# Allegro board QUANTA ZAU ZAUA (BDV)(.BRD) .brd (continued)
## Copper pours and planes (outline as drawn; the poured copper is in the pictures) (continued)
N18867812 on TOP (solid shape): outline of 127 points within 18.86,27.93 21.68,32.12
N21450006 on TOP (solid shape): 54.82,31.86 56.6,31.86 56.75,31.71 56.75,31.15 56.72,31.08 56.65,31.05 56.63,31.05 56.37,30.95 56.22,30.62 56.15,30.59 55.69,30.59 55.49,30.39 55.49,30.12 55.25,29.88 54.84,29.88 54.67,30.06 54.67,31.05 54.41,31.32 54.41,31.52 54.32,31.61 53.78,31.61 53.68,31.71 53.68,32.12 53.78,32.22 54.47,32.22
N22415444 on TOP (solid shape): 112.49,40.29 112.49,33.95 112.87,33.56 113.7,33.56 114.46,34.33 115.15,34.33 115.94,35.11 116.62,35.11 116.98,35.47 117.61,35.47 117.71,35.37 117.71,34.58 116.02,32.88 112.15,32.88 112.14,32.89 111.76,32.89 111.47,33.18 111.34,33.18 111.32,33.2 111.31,33.21 111.27,33.26 111.2,33.28 110.82,33.28 110.75,33.26 110.69,33.19 110.66,33.18 110.63,33.18 109.87,32.42 108.32,32.42 108.27,32.47 108.01,32.47 107.28,33.21 106.89,33.21 106.79,33.32 105.8,34.3 105.8,35.77 105.93,35.9 109.81,35.9 110.16,36.26 110.16,40.29 110.3,40.42 112.36,40.42
N22415444 on BOTTOM (solid shape): 111.55,40.19 111.55,36.63 111.55,36.61 111.54,36.6 110.26,35.32 106.15,35.32 105.54,35.93 105.54,36.9 105.61,37.02 105.63,37.15 105.61,37.28 105.55,37.39 105.54,37.4 105.54,37.55 105.55,37.56 105.61,37.67 105.62,37.79 105.6,37.91 105.54,38.03 105.54,38.26 105.54,38.29 105.66,38.43 105.69,38.59 105.66,38.75 105.54,38.9 105.54,38.92 105.54,40.33 105.73,40.51 106.17,40.51 106.34,40.68 111.07,40.68
N23833251 on BOTTOM (solid shape): 214.06,18.49 214.06,16.78 213.9,16.62 213.47,16.62 213.42,16.57 213.42,16.12 213.56,15.98 213.56,15.97 213.6,15.94 214.49,15.94 214.56,15.86 214.56,15.02 214.53,14.97 214.5,14.92 214.47,14.87 214.45,14.82 214.44,14.76 214.44,14.72 214.39,14.67 213.56,14.67 213.37,14.67 213.33,14.63 212.45,14.63 212.15,14.92 212.15,14.97 214.4,14.97 214.4,15.17 213.56,15.17 213.56,14.97 212.15,14.97 212.15,15.47 214.4,15.47 214.4,15.67 213.56,15.67 213.56,15.47 212.15,15.47 212.15,18.86 212.26,18.96 213.58,18.96
N24507636 on TOP (solid shape): 167.83,24.65 167.96,24.62 168.09,24.65 168.09,24.65 168.57,24.65 169.1,24.12 169.1,22.47 168.59,21.96 163.89,21.96 163.76,22.08 163.76,22.97 164.02,23.23 164.76,23.23 164.8,23.23 166.56,23.23 166.81,23.48 166.81,24.6 166.86,24.65 167.82,24.65
N24507636 on BOTTOM (solid shape): 168.46,23.74 168.59,23.74 168.63,23.72 168.65,23.72 169.04,23.72 169.06,23.72 169.1,23.74 169.23,23.74 169.44,23.52 169.44,22.88 169.86,22.47 170.5,22.47 171,22.97 171.51,22.97 171.64,22.85 171.64,21.58 171.38,21.32 167.07,21.32 166.81,21.58 166.81,23.99 166.94,24.12 168.08,24.12
N24742093 on BOTTOM (solid shape): outline of 112 points within 67.47,93.92 70.04,101.84
N24742107 on TOP (solid shape): 24.06,99.05 24.06,98.03 23.94,97.9 23.36,97.9 23.34,97.92 23.22,98 23.07,98.03 22.93,98 22.79,97.91 22.77,97.9 22.16,97.9 22.03,97.78 22.03,96.22 21.89,96.08 21.89,95.22 21.89,95.17 21.91,95.11 21.91,94.99 21.9,94.96 21.86,94.94 21.84,94.94 21.84,94.27 21.83,94.23 21.79,94.22 21.69,94.22 21.65,94.23 21.64,94.27 21.64,94.94 21.44,94.94 21.44,94.27 21.43,94.23 21.39,94.22 21.14,94.22 21.13,94.23 20.88,94.23 20.76,94.35 20.76,98.84 21.01,99.08 22.41,99.08 22.66,99.33 23.78,99.33
N24742181 on TOP (solid shape): 20.31,93.93 20.31,93.02 20.45,92.87 20.92,92.87 21,92.95 21.39,92.95 21.43,92.94 21.44,92.9 21.44,92.23 21.64,92.23 21.64,92.9 21.65,92.94 21.69,92.95 21.8,92.95 21.84,92.91 21.84,92.78 21.83,92.77 21.8,92.68 21.79,92.59 21.79,91.89 21.4,91.5 21.4,90.79 21.02,90.41 20.6,90.41 20.55,90.47 20.55,91.02 20.17,91.4 18.73,91.4 18.53,91.6 18.53,93.86 18.76,94.09 20.15,94.09
N24742181 on TOP (solid shape): 23.39,92.98 23.43,92.96 23.44,92.92 23.44,92.23 23.64,92.23 23.64,92.92 23.65,92.96 23.69,92.98 23.88,92.98 23.88,92.97 24.65,92.97 26.27,91.35 26.27,90.54 26.14,90.41 25.89,90.41 25.79,90.41 25.46,90.41 25.45,90.4 24.99,90.4 24.8,90.59 24.8,90.62 24.37,91.05 24.33,91.05 24.22,91.17 24.01,91.17 23.31,91.87 23.3,91.93 23.3,92.59 23.28,92.68 23.25,92.77 23.24,92.78 23.24,92.94 23.28,92.98
N24742181 on IN1 (solid shape): 26.1,91.52 26.1,90.53 26,90.43 24.2,90.43 23.48,91.15 19.98,91.15 19.58,91.55 19.58,92.15 20.01,92.58 25.04,92.58
N25430988 on TOP (solid shape): 30.75,10.93 30.75,9.06 30.45,8.77 28.88,8.77 28.26,9.39 28.26,11.01 28.36,11.11 30.57,11.11
N28087213 on TOP (solid shape): 39.69,112.76 39.69,111.87 39.56,111.75 26.94,111.75 26.17,110.98 25.5,110.98 25.26,111.22 25.26,112.05 26.1,112.89 39.56,112.89
N28087213 on BOTTOM (solid shape): 20.27,111.87 21.14,111.4 21.64,111.23 22.11,111.15 22.75,111.23 23.41,111.41 23.53,111.45 24.63,111.45 25.38,112.2 26.07,112.2 26.22,112.05 26.22,111.93 26.22,111.93 26.22,111.59 26.22,111.59 26.22,110.96 25.64,110.38 23.63,110.38 23.33,110.24 23.03,110.12 22.69,109.97 22.45,109.85 22.19,109.76 21.96,109.63 21.62,109.48 21.39,109.38 21.1,109.26 20.89,109.16 20.73,109.12 20.52,109.08 18.86,109.08 18.48,109.46 18.48,110.96 19.59,112.07 19.74,112.2
N30319022 on TOP (solid shape): 140.55,78.07 140.55,77.46 141.08,76.92 141.24,76.92 142.71,75.45 142.71,74.74 142.4,74.43 137.65,74.43 137.3,74.79 136.51,74.79 136.38,74.92 136.38,75.35 136.74,75.7 137.76,75.7 138.72,76.67 138.72,78.01 138.85,78.14 140.47,78.14
N30319022 on BOTTOM (solid shape): 138.58,78.13 142.57,78.13 142.66,78.04 142.66,77.15 142.68,77.13 142.68,74.74 142.39,74.45 134.75,74.45 133.03,76.16 133.03,78.4 133.31,78.68 138.03,78.68
N30442035 on TOP (solid shape): outline of 92 points within 18.07,22.13 22.29,26.58
N31069510 on TOP (solid shape): 155.7,26.15 155.74,26.13 155.75,26.1 155.75,25.38 155.95,25.38 155.95,26.1 155.96,26.13 156,26.15 157.03,26.15 157.05,26.14 157.38,26.14 158.33,25.18 158.33,25.16 158.46,24.89 158.73,24.76 158.75,24.76 159.14,24.37 159.98,24.37 160.16,24.19 160.16,23.05 159.98,22.87 159.04,22.87 158.28,23.63 156.48,23.63 156.35,23.76 156.35,23.96 156.27,24.04 156.27,24.11 156.2,24.27 156.04,24.34 155.97,24.34 155.51,24.8 155.51,25.35 155.54,25.38 155.55,25.38 155.55,26.06 155.64,26.15
N31353058 on TOP (solid shape): 37.6,30.52 37.6,28.79 38.1,28.29 38.1,27.89 38.07,27.86 38.05,27.84 37.64,27.84 37.61,27.84 37.58,27.82 37.5,27.82 37.4,27.72 37.06,27.72 36.97,27.72 36.71,27.72 36.36,27.37 36.36,27.09 36.21,26.94 35.55,26.94 35.44,27.04 35.44,27.75 35.46,27.78 35.75,27.92 35.85,28.18 35.74,28.45 35.47,28.56 35.42,28.56 35.38,28.55 35.27,28.56 35.16,28.54 35.15,28.54 34.99,28.54 34.9,28.6 34.79,28.63 34.78,28.64 34.73,28.64 34.46,28.53 34.35,28.26 34.34,28.22 34.25,28.13 33.11,28.13 32.97,28.22 32.81,28.25 32.65,28.22 32.51,28.13 32.35,28.13 32.21,28.22 32.05,28.25 31.93,28.24 31.82,28.19 31.78,28.18 31.75,28.2 31.61,28.33 31.43,28.38 31.25,28.34 31.1,28.21 31.08,28.21 30.65,28.21 30.53,28.09 30.53,27.9 30.18,27.55 29.55,27.55 29.4,27.7 29.4,28 28.94,28.46 28.94,29.48 28.99,29.53 33.29,29.53 33.46,29.35 36,29.35 36.23,29.58 36.23,30.54 36.38,30.69 37.43,30.69
N37568058 on TOP (solid shape): 125.06,122.57 125.06,121.12 125.02,121.08 123.57,121.08 122.41,122.24 122.41,122.95 122.52,123.05 124.57,123.05
N38517597 on TOP (solid shape): 18.73,13.68 18.73,11.8 18.83,11.7 19.52,11.7 19.62,11.59 19.62,10.7 19.49,10.58 18.81,10.58 17.51,11.87 17.16,11.87 17.06,11.98 17.06,12.53 17.18,12.66 17.72,12.66 18.1,13.04 18.1,13.65 18.15,13.7 18.71,13.7
N39168858 on TOP (solid shape): 26.86,74.23 26.88,74.23 27.02,74.12 27.17,74.08 27.19,74.08 27.52,73.75 27.52,72.48 27.16,72.12 26.25,72.12 26.15,72.23 26.15,74.15 26.22,74.23
N39168858 on IN3 (solid shape): 26.24,74.82 26.24,74.8 26.37,74.63 26.58,74.56 26.63,74.56 26.68,74.57 26.77,74.56 26.81,74.47 26.81,74.46 26.92,74.19 27.19,74.08 27.23,74.08 27.31,74.05 27.34,73.98 27.54,73.78 27.54,73.19 27.27,72.91 26.37,72.91 25.06,74.22 25.06,74.59 25.31,74.84 26.21,74.84
N39687060 on TOP (solid shape): 66.64,118.43 66.64,117.41 67.51,116.53 67.66,116.53 67.86,116.33 67.86,116.1 67.7,115.94 66.27,115.94 65.82,116.39 65.82,118.3 65.67,118.45 65.67,118.55 65.69,118.58 65.72,118.6 66.46,118.6
N39687064 on TOP (solid shape): 59.5,124.55 60.31,124.55 60.54,124.78 60.97,124.78 61.05,124.7 61.05,121.5 61.53,121.02 61.66,121.02 61.68,121 62.63,121 62.7,121.07 62.7,121.19 62.75,121.25 63.94,121.25 64.02,121.17 64.02,116.88 64.27,116.62 64.63,116.62 64.76,116.5 64.76,116.09 64.63,115.96 62.24,115.96 62.14,116.06 62.14,116.75 62.22,116.83 63.31,116.83 63.71,117.23 63.71,118.48 63.61,118.58 62.8,118.58 62.75,118.63 62.75,119.49 62.64,119.6 61.68,119.6 61.68,119.59 57.34,119.59 57.13,119.8 62.46,119.8 62.46,120 61.68,120 61.68,119.8 57.13,119.8 56.81,120.13 56.81,120.2 62.46,120.2 62.46,120.4 61.68,120.4 61.68,120.2 56.81,120.2 56.81,120.6 62.46,120.6 62.46,120.8 61.68,120.8 61.68,120.6 56.81,120.6 56.81,124.29 57.29,124.78 59.27,124.78
N39687102 on TOP (solid shape): 52.46,123.75 52.89,123.75 52.99,123.7 53.1,123.68 53.27,123.73 53.42,123.86 53.45,123.86 54.75,123.86 54.94,123.67 54.94,123.67 55.01,123.57 55.11,123.5 55.12,123.49 55.28,123.33 55.28,119.26 54.42,118.4 52.23,118.4 51.68,118.96 51.68,118.96 50.1,120.53 50.1,120.53 49.34,121.3 49.34,122.46 49.46,122.59 50.81,122.59 51.14,122.93 51.14,123.68 51.32,123.86 52.34,123.86
N39687102 on BOTTOM (solid shape): 56.68,123.4 56.98,123.4 57.08,123.3 57.08,122.54 56.83,122.29 56.3,122.29 54.95,120.94 54.95,118.02 53.43,116.5 49.31,116.5 49.05,116.76 49.05,122.36 49.59,122.9 50.73,122.9 51.26,123.42 56.67,123.42
N39687482 on TOP (solid shape): 67.5,125.23 67.63,125.21 67.76,125.23 67.76,125.23 68.17,125.23 68.21,125.22 68.25,125.21 68.32,125.2 68.65,124.86 68.74,124.82 69.44,124.82 71.16,123.1 71.16,120.48 70.12,119.44 70.06,119.44 69.18,120.33 69.18,120.61 69.81,121.25 69.81,122.49 69.78,122.52 69.78,122.54 69.71,122.7 69.55,122.77 69.25,122.77 69.16,122.75 69.09,122.69 69.08,122.69 69.04,122.67 68.79,122.67 68.01,123.46 68.01,123.93 68.01,124.07 67.97,124.1 67.97,124.11 67.83,124.27 67.63,124.32 67.36,124.21 67.24,123.94 67.24,123.82 67.24,123.81 67.24,123.38 66.79,122.92 66.39,122.92 66.05,122.58 65.45,122.58 65.21,122.35 65.21,121.63 65.09,121.5 64.63,121.5 64.59,121.51 64.58,121.55 64.58,122.29 64.55,122.31 64.55,122.47 64.56,122.49 64.57,122.5 64.9,122.83 65.52,123.46 66.02,123.46 66.36,123.8 66.36,124.46 66.37,124.48 66.38,124.49 66.58,124.7 66.66,124.7 66.75,124.74 66.78,124.83 66.78,124.95 67.02,125.18 67.03,125.18 67.11,125.2 67.18,125.23 67.49,125.23

Small or netless copper shapes (teardrops, artwork), in the pictures only: 10 on TOP, 60 on BOTTOM, 68 on IN2, 16 on IN3

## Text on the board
Ref Des/Silkscreen Bottom: MODEL:ZAU | REV:D | DA0ZAUMB8D0
User.Comments: OUTLINE | 16x35 | 26x33 | 33x37
Ref Des/Silkscreen Top: DA0ZAUMB8D0 REV:D
User.8: 145 | 219.8 | 128
User.12: +VCCHDA | +5V | VA | +1.2VSUS | +3V | +VGPU_CORE | +1V_S5 | +3V_S5 | +5V_S5 | ADOGND | GND | +VCCGT | +VCC_CORE | +VCCSA
User.28: ADOGND | GND
User.29: ADOGND | GND
User.31: REV:A-6
User.45: Excess check:Jan 17 11:23:18 2019 | No Route Under Component:Mar 05 18:09:46 2019 | PadStack_Check:Mar 05 17:49:51 2019 | TP check:Mar 05 17:50:01 2019 | XY-Check acute:Mar 05 17:59:59 2019 | XY-Create nettxt:Nov 21 14:33:51 2018 | XY-Create plane:Jan 17 11:31:55 2019 | XY-Cross plane-BOTTOM-SGND1:Mar 05 18:03:16 2019 | XY-Cross plane-IN1-SGND:Mar 05 18:02:49 2019 | XY-Cross plane-IN2-SVCC:Mar 05 18:02:53 2019 | XY-Cross plane-IN3-SGND1:Mar 05 18:02:58 2019 | XY-Cross plane-IN3-SVCC:Mar 05 18:03:05 2019 | XY-Cross plane-TOP-SGND:Mar 05 18:02:42 2019 | XY-Dxf to pin check:Mar 05 17:56:05 2019 | XY-Etch cross-IN1-IN2:Mar 05 18:02:46 2019 | XY-Etch ref-BOTTOM-SGND1:Mar 05 18:03:23 2019 | XY-Etch ref-IN1-SGND:Mar 05 18:02:52 2019 | XY-Etch ref-IN2-SVCC:Mar 05 18:02:58 2019 | XY-Etch ref-IN3-SGND1:Mar 05 18:03:05 2019 | XY-Etch ref-IN3-SVCC:Mar 05 18:03:16 2019 | XY-Etch ref-TOP-SGND:Mar 05 18:02:45 2019 | XY-Excess check:Feb 27 15:51:18 2019 | XY-NO Route Under Component:Mar 05 18:09:46 2019 | XY-Outline check:Mar 05 18:10:17 2019 | XY-PadStack_Check:Mar 05 17:49:51 2019 | XY-Plane net check:Mar 05 17:57:53 2019 | XY-Prop check:Jan 17 11:25:23 2019 | XY-Symbol cross:Nov 24 17:33:45 2018 | XY-TP check:Mar 05 17:50:01 2019 | XY-shape min check:Mar 05 17:48:15 2019 | XY-shape pin check:Nov 24 18:29:22 2018 | XY-via check:Mar 05 18:07:17 2019 | check acute:Mar 05 17:59:59 2019 | create plane:Jan 17 11:31:55 2019 | cross plane-BOTTOM-SGND1:Mar 05 18:03:16 2019 | cross plane-IN1-SGND:Mar 05 18:02:49 2019 | cross plane-IN2-SVCC:Mar 05 18:02:53 2019 | cross plane-IN3-SGND1:Mar 05 18:02:58 2019 | cross plane-IN3-SVCC:Mar 05 18:03:05 2019 | cross plane-TOP-SGND:Mar 05 18:02:42 2019 | dxf to pin check:Mar 05 17:56:05 2019 | etch cross-IN1-IN2:Mar 05 18:02:46 2019 | etch ref-BOTTOM-SGND1:Mar 05 18:03:23 2019 | etch ref-IN1-SGND:Mar 05 18:02:52 2019 | etch ref-IN2-SVCC:Mar 05 18:02:58 2019 | etch ref-IN3-SGND1:Mar 05 18:03:05 2019 | etch ref-IN3-SVCC:Mar 05 18:03:16 2019 | etch ref-TOP-SGND:Mar 05 18:02:45 2019 | outline check:Mar 05 18:10:17 2019 | plane net check:Mar 05 17:57:53 2019 | prop check:Jan 17 11:25:23 2019 | shape min check:Mar 05 17:48:15 2019 | via check:Mar 05 18:07:17 2019 | ZAU-MB | DATE | 03/06/19' | PROJECT | LAYER | REV. | SVCC | IN1 | IN2 | IN3 | TOP | C | 1 | 3 | 4 | 5 | 6 | 8 | BOTTOM | FIGURE | TYPE | Circle | Oblong | Rectangle | SIZE | 10.0 | 12.0 | 14.0 | 16.0 | 22.0 | 32.0 | 35.0 | 102.0 | 118.0 | 126.0 | 150.0 | 220.0 | 26.0 | 41.0 | 43.0 | 47.0 | 63.0 | 67.0 | 75.0 | 98.0 | 43.0x20.0 | 59.0x20.0 | 59.0x28.0 | 63.0x31.0 | 71.0x31.0 | 75.0x39.0 | 91.0x28.0 | 102.0x31.0 | 118.0x20.0 | 252.0x232.0 | 158.0x158.0 | DRILL CHART: TOP to BOTTOM | ALL UNITS ARE IN MILS | PLATED | NON-PLATED | ROTATION | - | 90.000 | 0.000 | QTY | 5374 | 19 | 70 | 48 | 10 | 18 | 2 | 5592 | 33 | TOTAL HOLES: | DA0ZAUMB8C0 | 17.2
